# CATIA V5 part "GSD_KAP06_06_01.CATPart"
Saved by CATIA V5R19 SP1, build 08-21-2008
Part number: GSD_OFFSET_03
Definition: Beispielmodell für Funktionen Übergang, Füllen und Offset.
Description: CATIA V5 Flächenmodellierung  Copyright (c) 2009 Maik Hertha IT Consultants
Bounding box of the stored display mesh (mm): x 0 to 49.234, y 0 to 47.42, z 0 to 65.132
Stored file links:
  \GSD_BUCH_UEBUNG\GSD_KAP06_06_01.CATPart
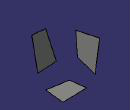
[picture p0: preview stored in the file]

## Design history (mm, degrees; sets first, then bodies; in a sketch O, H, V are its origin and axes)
AxisSystem1 "Absolute Axis System": origin (0, 0, 0), X (1, 0, 0), Y (0, 1, 0), Z (0, 0, 1)
Set1 "Planes.1"
  Plane1: type Equation, A 0, B 1, C 0, Length 0
  Plane2: type Equation, A 0, B 0, C 1, Length 0
  Plane3: type Equation, A 1, B 0, C 0, Length 0
Set2 "Skizzen.1"
  Sketch1 on Plane1, origin (0, 0, 0), H (-1, 0, 0), V (0, 0, 1)
    line L1 (-40.7892, 13.7277) -> (-49.2341, 65.1316)
    line L2 (-49.2341, 65.1316) -> (-29.5293, 63.051)
    line L3 (-29.5293, 63.051) -> (-14.1082, 15.4412)
    line L4 (-14.1082, 15.4412) -> (-40.7892, 13.7277)
  Sketch2 on Plane3, origin (0, 0, 0), H (0, 1, 0), V (0, 0, 1)
    line L1 (16.0881, 21.2572) -> (13.3955, 53.2011)
    line L2 (13.3955, 53.2011) -> (47.42, 60.6669)
    line L3 (47.42, 60.6669) -> (41.3005, 12.9347)
    line L4 (41.3005, 12.9347) -> (16.0881, 21.2572)
  Sketch3 on Plane2, origin (0, 0, 0), H (1, 0, 0), V (0, 1, 0)
    line L1 (12.7396, 17.2746) -> (9.9246, 38.9377)
    line L2 (9.9246, 38.9377) -> (44.561, 39.7944)
    line L3 (44.561, 39.7944) -> (41.746, 12.379)
    line L4 (41.746, 12.379) -> (12.7396, 17.2746)
Set3 "Basisflaechen.1"
  Split1: ToCut Plane1, Cutting Sketch1
  Split2: ToCut Plane3, Cutting Sketch2
  Split3: ToCut Plane2, Cutting Sketch3
Body1 (main body)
